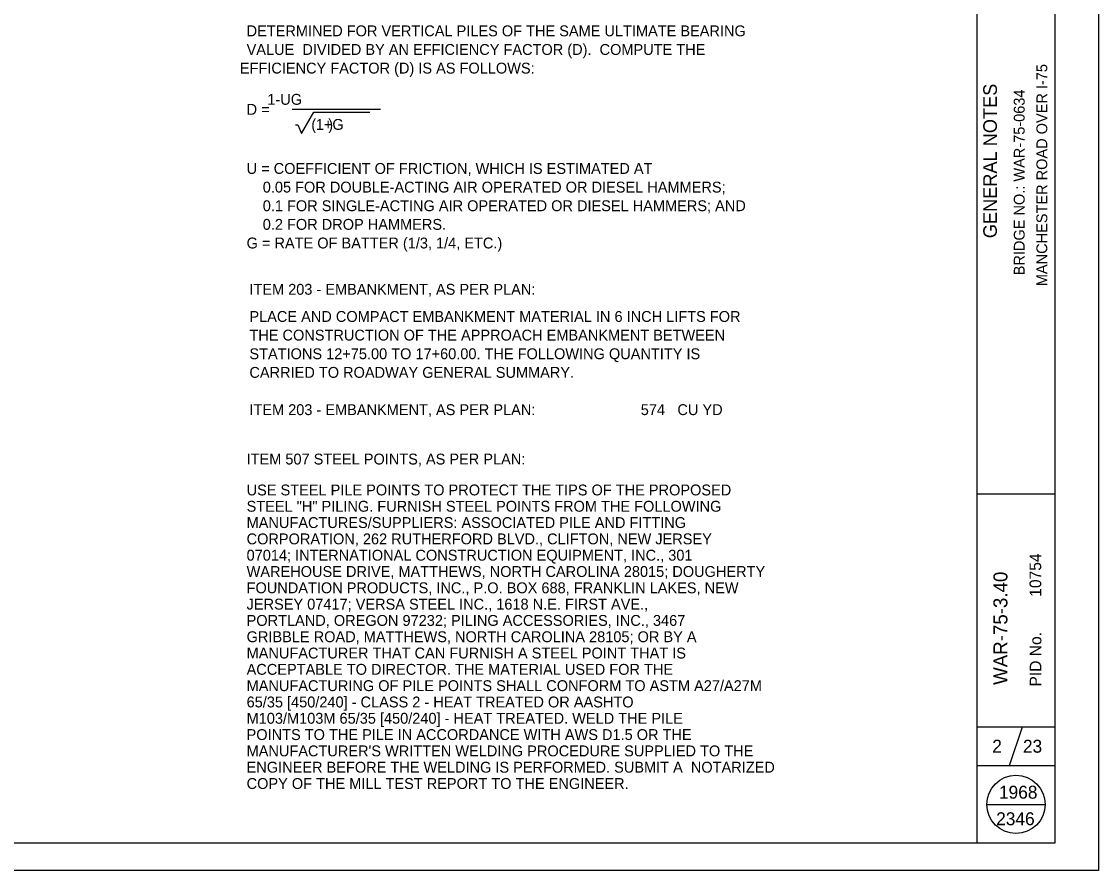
# Model space of a CAD drawing. Extents: x -70.8 to -34.9, y -11.3 to 10.7.
# Drawn here: x -49.38 to -35.51, y -11.12 to -0.19 of the extents above; entities that cross this region are included whole.
import ezdxf

# ---------------------------------------------------------------- set-up
doc = ezdxf.new("R2010")
doc.units = 0
for name, color, linetype in [('BR_P_Gen_Text', 7, 'Continuous'), ('SH_Border', 7, 'Continuous'), ('SH_Cut_Line', 7, 'Continuous'), ('SH_Data', 7, 'Continuous')]:
    doc.layers.add(name, color=color, linetype=linetype)

msp = doc.modelspace()

# ---------------------------------------------------------------- linework, layer by layer
at = {"layer": 'BR_P_Gen_Text'}
msp.add_line((-45.891, -1.321), (-44.754, -1.321), dxfattribs=at)
msp.add_lwpolyline([(-45.851, -1.523), (-45.818, -1.523), (-45.772, -1.635), (-45.613, -1.362), (-44.891, -1.362)], dxfattribs=at)
at = {"layer": 'SH_Border'}
for p, q in [((-37.071, -10.774), (-37.071, 10.226)), ((-37.071, -6.274), (-36.071, -6.274)), ((-37.071, -9.274), (-36.071, -9.274)), ((-36.654, -9.774), (-36.488, -9.274)), ((-37.071, -9.774), (-36.071, -9.774))]:
    msp.add_line(p, q, dxfattribs=at)
msp.add_lwpolyline([(-67.571, 10.226), (-36.071, 10.226), (-36.071, -10.774), (-67.571, -10.774)], close=True, dxfattribs=at)
at = {"layer": 'SH_Cut_Line'}
msp.add_lwpolyline([(-35.509, -11.124), (-69.509, -11.124), (-69.509, 10.526), (-35.509, 10.526)], close=True, dxfattribs=at)
at = {"layer": 'SH_Data'}
msp.add_line((-36.946, -10.274), (-36.196, -10.274), dxfattribs=at)
msp.add_circle((-36.571, -10.274), 0.375, dxfattribs=at)

# ---------------------------------------------------------------- texts
at = {"layer": 'BR_P_Gen_Text'}
for s, p in [('DETERMINED FOR VERTICAL PILES OF THE SAME ULTIMATE BEARING ', (-46.479, -0.383)), ('VALUE  DIVIDED BY AN EFFICIENCY FACTOR (D).  COMPUTE THE ', (-46.479, -0.623)), (' EFFICIENCY FACTOR (D) IS AS FOLLOWS:', (-46.618, -0.863)), ('       1-UG', (-46.576, -1.265)), ('D = ', (-46.479, -1.394)), ('(   )', (-45.646, -1.588)), ('1+G', (-45.588, -1.588)), ('U = COEFFICIENT OF FRICTION, WHICH IS ESTIMATED AT ', (-46.479, -2.155)), ('    0.05 FOR DOUBLE-ACTING AIR OPERATED OR DIESEL HAMMERS; ', (-46.479, -2.395)), ('    0.1 FOR SINGLE-ACTING AIR OPERATED OR DIESEL HAMMERS; AND ', (-46.479, -2.635)), ('    0.2 FOR DROP HAMMERS.', (-46.479, -2.875)), ('G = RATE OF BATTER (1/3, 1/4, ETC.)', (-46.479, -3.115)), ('ITEM 203 - EMBANKMENT, AS PER PLAN:', (-46.443, -3.711)), ('PLACE AND COMPACT EMBANKMENT MATERIAL IN 6 INCH LIFTS FOR', (-46.443, -4.061)), ('THE CONSTRUCTION OF THE APPROACH EMBANKMENT BETWEEN ', (-46.443, -4.301)), ('STATIONS 12+75.00 TO 17+60.00. THE FOLLOWING QUANTITY IS ', (-46.443, -4.541)), ('CARRIED TO ROADWAY GENERAL SUMMARY.', (-46.443, -4.781)), ('ITEM 203 - EMBANKMENT, AS PER PLAN: ', (-46.443, -5.261)), ('574', (-41.403, -5.261)), (' CU YD', (-40.983, -5.261)), ('ITEM 507 STEEL POINTS, AS PER PLAN:', (-46.479, -5.897)), ('USE STEEL PILE POINTS TO PROTECT THE TIPS OF THE PROPOSED  ', (-46.479, -6.295)), ('STEEL "H" PILING. FURNISH STEEL POINTS FROM THE FOLLOWING  ', (-46.479, -6.505)), ('MANUFACTURES/SUPPLIERS: ASSOCIATED PILE AND FITTING  ', (-46.479, -6.715)), ('CORPORATION, 262 RUTHERFORD BLVD., CLIFTON, NEW JERSEY  ', (-46.479, -6.925)), ('07014; INTERNATIONAL CONSTRUCTION EQUIPMENT, INC., 301  ', (-46.479, -7.135)), ('WAREHOUSE DRIVE, MATTHEWS, NORTH CAROLINA 28015; DOUGHERTY  ', (-46.479, -7.345)), ('FOUNDATION PRODUCTS, INC., P.O. BOX 688, FRANKLIN LAKES, NEW  ', (-46.479, -7.555)), ('JERSEY 07417; VERSA STEEL INC., 1618 N.E. FIRST AVE.,  ', (-46.479, -7.765)), ('PORTLAND, OREGON 97232; PILING ACCESSORIES, INC., 3467  ', (-46.479, -7.975)), ('GRIBBLE ROAD, MATTHEWS, NORTH CAROLINA 28105; OR BY A  ', (-46.479, -8.185)), ('MANUFACTURER THAT CAN FURNISH A STEEL POINT THAT IS  ', (-46.479, -8.395)), ('ACCEPTABLE TO DIRECTOR. THE MATERIAL USED FOR THE  ', (-46.479, -8.605)), ('MANUFACTURING OF PILE POINTS SHALL CONFORM TO ASTM A27/A27M  ', (-46.479, -8.815)), ('65/35 [450/240] - CLASS 2 - HEAT TREATED OR AASHTO  ', (-46.479, -9.025)), ('M103/M103M 65/35 [450/240] - HEAT TREATED. WELD THE PILE  ', (-46.479, -9.235)), ('POINTS TO THE PILE IN ACCORDANCE WITH AWS D1.5 OR THE  ', (-46.479, -9.445)), ("MANUFACTURER'S WRITTEN WELDING PROCEDURE SUPPLIED TO THE  ", (-46.479, -9.655)), ('ENGINEER BEFORE THE WELDING IS PERFORMED. SUBMIT A  NOTARIZED  ', (-46.479, -9.865)), ('COPY OF THE MILL TEST REPORT TO THE ENGINEER. ', (-46.479, -10.075))]:
    msp.add_text(s, height=0.14, dxfattribs=at).set_placement(p)
at = {"layer": 'SH_Data'}
for s, height, p in [('MANCHESTER ROAD OVER I-75', 0.14, (-36.168, -3.601)), ('GENERAL NOTES', 0.175, (-36.817, -2.983)), ('BRIDGE NO.: WAR-75-0634', 0.14, (-36.459, -3.461)), (' 10754', 0.15, (-36.246, -7.656)), ('WAR-75-3.40', 0.18, (-36.681, -8.735)), ('PID No.', 0.15, (-36.244, -8.756))]:
    msp.add_text(s, height=height, rotation=90, dxfattribs=at).set_placement(p)
for s, height, p in [('2', 0.167, (-36.877, -9.608)), (' 23', 0.1666, (-36.543, -9.608)), ('1968', 0.1666, (-36.79, -10.2)), ('2346', 0.1666, (-36.826, -10.542))]:
    msp.add_text(s, height=height, dxfattribs=at).set_placement(p)

doc.saveas('drawing.dxf')
